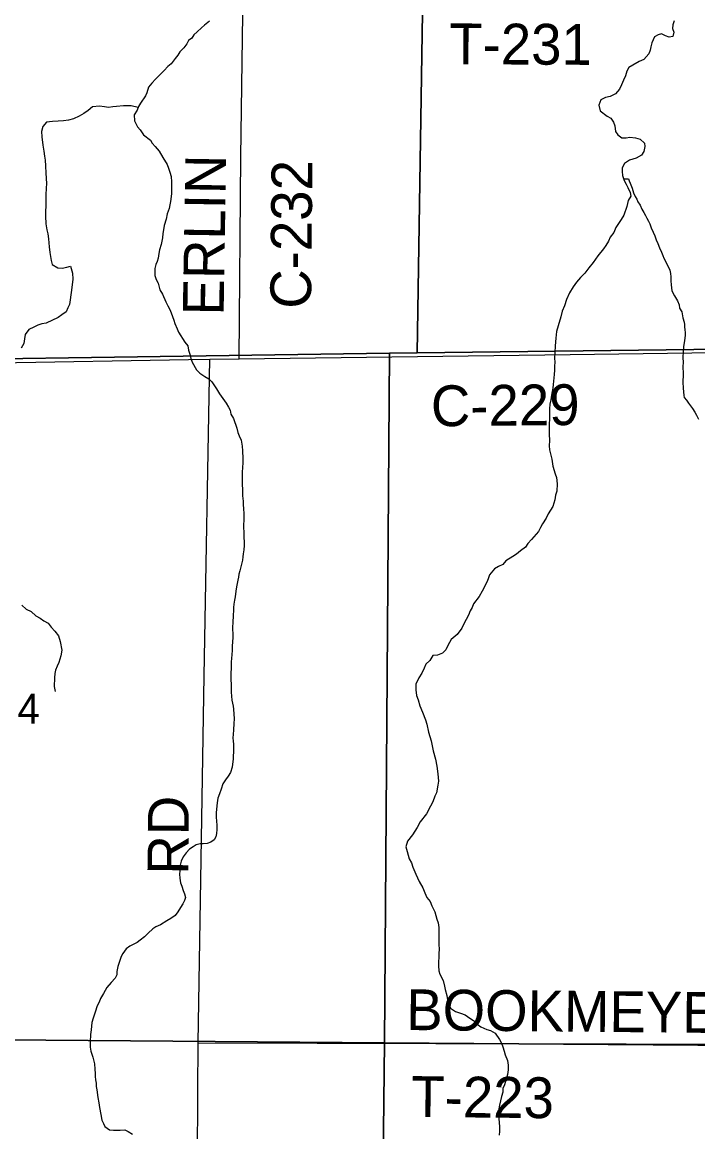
# Model space of a CAD drawing. Extents: x 0 to 34, y 0 to 22.
# Drawn here: x 28.499 to 29.44, y 18.79 to 20.335 of the extents above; entities that cross this region are included whole.
import ezdxf

# ---------------------------------------------------------------- set-up
doc = ezdxf.new("R2010")
doc.units = 0
for name, color, linetype in [('GM_X_County_Road', 7, 'Continuous'), ('GM_X_County_Road_Text', 7, 'Continuous'), ('GM_X_Minor_River', 7, 'Continuous'), ('GM_X_Section', 7, 'Continuous'), ('GM_X_Section_Text', 7, 'Continuous'), ('GM_X_Township_Road', 7, 'Continuous'), ('GM_X_Township_Road_Text', 7, 'Continuous')]:
    doc.layers.add(name, color=color, linetype=linetype)

msp = doc.modelspace()

# ---------------------------------------------------------------- linework, layer by layer
at = {"layer": 'GM_X_County_Road'}
for p, q in [((28.801, 19.8664), (29.2621, 19.8726)), ((28.0544, 19.8539), (28.7306, 19.8653)), ((28.7306, 19.8653), (28.76, 19.8658)), ((28.7525, 19.4249), (28.76, 19.8658)), ((28.76, 19.8658), (28.801, 19.8664))]:
    msp.add_line(p, q, dxfattribs=at)
for points in [[(28.801, 19.8664), (28.8036, 20.1477), (28.8064, 20.346), (28.8073, 20.3551), (28.8077, 20.357), (28.8082, 20.3596), (28.8093, 20.3615), (28.8128, 20.3664), (28.8151, 20.3682), (29.0351, 20.3742), (29.0559, 20.3746), (29.0644, 20.8767), (29.0647, 20.9)], [(29.2621, 19.8726), (30.0076, 19.8826), (30.0335, 19.8831)], [(28.739, 18.4414), (28.7392, 18.4501), (28.7405, 18.537), (28.7417, 18.6373), (28.7429, 18.7487), (28.7437, 18.8464), (28.7439, 18.9139), (28.7525, 19.4249)]]:
    msp.add_lwpolyline(points, dxfattribs=at)
at = {"layer": 'GM_X_Minor_River'}
for points in [[(28.7598, 20.3365), (28.7526, 20.3309), (28.7484, 20.3275), (28.7426, 20.3219), (28.738, 20.3178), (28.7353, 20.3129), (28.7307, 20.3095), (28.7284, 20.305), (28.7241, 20.2997), (28.7184, 20.2941), (28.7157, 20.2892), (28.7118, 20.2847), (28.7064, 20.2771), (28.7018, 20.2734), (28.6965, 20.2677), (28.6903, 20.2613), (28.6846, 20.2557), (28.6796, 20.2505), (28.675, 20.2448), (28.6726, 20.2369), (28.6707, 20.2327), (28.6637, 20.2225), (28.661, 20.218), (28.659, 20.2127), (28.6548, 20.2063), (28.6555, 20.1979), (28.6595, 20.1896), (28.6633, 20.1853), (28.6678, 20.1785), (28.6775, 20.1711), (28.6801, 20.1666), (28.6843, 20.1623), (28.6895, 20.1554), (28.6947, 20.147), (28.7007, 20.1371), (28.7029, 20.1321), (28.7047, 20.1264), (28.7062, 20.1203), (28.7068, 20.1131), (28.7067, 20.0968), (28.7062, 20.0926), (28.7054, 20.0854), (28.7046, 20.0809), (28.7034, 20.0756), (28.701, 20.0684), (28.6994, 20.0608), (28.6967, 20.0521), (28.6955, 20.0461), (28.695, 20.0411), (28.6942, 20.0347), (28.6926, 20.0256), (28.6902, 20.018), (28.6894, 20.0131), (28.6882, 20.0066), (28.687, 20.0021), (28.685, 19.9976), (28.6835, 19.9923), (28.6837, 19.9824), (28.6856, 19.9767), (28.6882, 19.9717), (28.6907, 19.9626), (28.6941, 19.9565), (28.6992, 19.9458), (28.7018, 19.9401), (28.7048, 19.934), (28.7081, 19.9256), (28.71, 19.9202), (28.7114, 19.9157), (28.7148, 19.908), (28.7166, 19.9035), (28.7255, 19.8897), (28.7297, 19.8843), (28.7307, 19.8783), (28.7329, 19.8714), (28.734, 19.8668), (28.7358, 19.8619), (28.7418, 19.8512), (28.7463, 19.8466), (28.7531, 19.842), (28.7587, 19.8385), (28.7628, 19.8343), (28.7658, 19.8301), (28.7696, 19.8247), (28.7737, 19.8178), (28.7785, 19.8113), (28.783, 19.8048), (28.7863, 19.7991), (28.7886, 19.7949), (28.7893, 19.7896), (28.793, 19.7835), (28.7978, 19.7697), (28.7992, 19.764), (28.8011, 19.7594)], [(29.4066, 20.3372), (29.4047, 20.3315), (29.4046, 20.3262), (29.4064, 20.3212), (29.4049, 20.3152), (29.3999, 20.3145), (29.3946, 20.3164), (29.3893, 20.3191), (29.3844, 20.3177), (29.3794, 20.3147), (29.3755, 20.3064), (29.374, 20.3011), (29.3735, 20.2962), (29.3716, 20.2909), (29.3647, 20.2833), (29.3578, 20.2804), (29.349, 20.2755), (29.3437, 20.2722), (29.341, 20.2669), (29.339, 20.2605), (29.3363, 20.2544), (29.3332, 20.248), (29.3308, 20.242), (29.325, 20.2352), (29.3174, 20.2318), (29.3113, 20.2304), (29.3048, 20.227), (29.3017, 20.2195), (29.3039, 20.2119), (29.3133, 20.2042), (29.3186, 20.2015), (29.3223, 20.1961), (29.3242, 20.1908), (29.3252, 20.1832), (29.3282, 20.1782), (29.3338, 20.1743), (29.3399, 20.1743), (29.3452, 20.175), (29.3528, 20.1741), (29.3592, 20.1722), (29.3652, 20.1668), (29.3659, 20.1619), (29.3647, 20.155), (29.3612, 20.1501), (29.354, 20.146), (29.3445, 20.1431), (29.3376, 20.1386), (29.3345, 20.1326), (29.3341, 20.1273), (29.3347, 20.1216), (29.3369, 20.1147), (29.3399, 20.1097), (29.3421, 20.1048), (29.3455, 20.0979), (29.3466, 20.093), (29.3427, 20.0869), (29.3407, 20.0786), (29.3368, 20.0665), (29.3329, 20.0605), (29.3291, 20.0548), (29.3256, 20.0492), (29.3225, 20.0424), (29.3178, 20.036), (29.3155, 20.0303), (29.3116, 20.0243), (29.3085, 20.0194), (29.3005, 20.01), (29.2939, 20.0005), (29.2878, 19.993), (29.2824, 19.9859), (29.2762, 19.9795), (29.2705, 19.9731), (29.2662, 19.9667)], [(28.6604, 20.2164), (28.6508, 20.2185), (28.6402, 20.2186), (28.6303, 20.2176), (28.625, 20.2173), (28.6193, 20.2166), (28.6136, 20.2174), (28.6064, 20.2182), (28.5969, 20.2172), (28.5908, 20.2123), (28.5846, 20.2082), (28.5782, 20.2045), (28.5705, 20.2004), (28.5633, 20.1986), (28.5565, 20.1979), (28.5489, 20.1972), (28.5413, 20.1969), (28.5329, 20.1958), (28.5275, 20.1898), (28.5259, 20.183), (28.5262, 20.1754), (28.5276, 20.164), (28.529, 20.1556), (28.5301, 20.1488), (28.5308, 20.1431), (28.5315, 20.1351), (28.5321, 20.1249), (28.5327, 20.1108), (28.5322, 20.104), (28.5321, 20.0949), (28.5317, 20.0858), (28.5314, 20.0649), (28.5321, 20.0546), (28.5331, 20.0459), (28.5346, 20.0406), (28.5356, 20.0333), (28.5366, 20.0223), (28.5377, 20.0147), (28.5384, 20.009), (28.5394, 20.0033), (28.5409, 19.9976), (28.5484, 19.9933), (28.5545, 19.9929), (28.561, 19.994), (28.5663, 19.9954), (28.5688, 19.9855), (28.5695, 19.9772), (28.5678, 19.962), (28.5649, 19.9423), (28.5626, 19.9374), (28.5603, 19.9321), (28.5541, 19.9276), (28.5492, 19.9242), (28.5324, 19.9161), (28.5263, 19.915), (28.5206, 19.9132), (28.5152, 19.9106), (28.5084, 19.9072), (28.503, 19.9001), (28.5022, 19.8944), (28.5013, 19.8876), (28.4975, 19.8811)], [(29.3361, 20.1172), (29.3432, 20.1171), (29.344, 20.1141), (29.3455, 20.111), (29.3482, 20.1042), (29.3501, 20.0978), (29.3524, 20.0924), (29.3547, 20.0887), (29.3563, 20.0852), (29.3593, 20.0803), (29.3616, 20.075), (29.3643, 20.0701), (29.3666, 20.0659), (29.3685, 20.0621), (29.3708, 20.058), (29.3728, 20.0542), (29.3747, 20.0489), (29.3774, 20.0428), (29.3797, 20.0379), (29.3816, 20.0322), (29.3839, 20.0269), (29.3862, 20.0212), (29.3889, 20.0151), (29.3908, 20.0102), (29.3924, 20.0068), (29.3943, 20.0034), (29.3966, 19.9981), (29.3989, 19.9939), (29.4008, 19.9897), (29.4016, 19.9852), (29.402, 19.9806), (29.402, 19.9745), (29.4024, 19.97), (29.4028, 19.9647), (29.4036, 19.9616), (29.4047, 19.9582), (29.4074, 19.9541), (29.4113, 19.9472), (29.4139, 19.9416), (29.4143, 19.937), (29.4174, 19.9317), (29.4178, 19.929), (29.419, 19.9237), (29.4205, 19.9173), (29.4209, 19.9142), (29.4213, 19.9116), (29.4217, 19.9063), (29.4221, 19.9036), (29.4221, 19.8994), (29.421, 19.8914), (29.4199, 19.8838), (29.4192, 19.8755), (29.4189, 19.869), (29.4193, 19.8603), (29.4189, 19.8565), (29.4189, 19.8531), (29.4193, 19.8481), (29.4194, 19.8447), (29.419, 19.8341), (29.4191, 19.8257), (29.4203, 19.8155), (29.4207, 19.8124), (29.4237, 19.809), (29.4268, 19.8049), (29.4321, 19.7973), (29.4356, 19.792), (29.4379, 19.7878), (29.4406, 19.7825)], [(29.2662, 19.9667), (29.2612, 19.9584), (29.2569, 19.9489), (29.2542, 19.9402), (29.2507, 19.933), (29.2487, 19.9247), (29.2451, 19.9126), (29.2431, 19.9047), (29.2419, 19.8952), (29.241, 19.8846), (29.2405, 19.8751), (29.24, 19.8671), (29.2404, 19.8622), (29.2403, 19.8557), (29.2399, 19.8508), (29.2398, 19.8447), (29.2394, 19.8398), (29.2381, 19.8307), (29.2377, 19.8258), (29.2369, 19.8208), (29.2357, 19.8159), (29.2348, 19.8095), (29.2336, 19.8034), (29.2332, 19.797), (29.2328, 19.7617), (29.233, 19.7525), (29.2326, 19.7453), (29.2333, 19.7396), (29.2351, 19.7324), (29.2362, 19.7267), (29.238, 19.7172), (29.2412, 19.7061), (29.2427, 19.7012), (29.2437, 19.6924), (29.2432, 19.6822), (29.2413, 19.6765), (29.2405, 19.6701), (29.2377, 19.661), (29.2315, 19.6504), (29.2284, 19.6444), (29.2234, 19.6365), (29.2207, 19.6316), (29.2176, 19.6259), (29.208, 19.615), (29.203, 19.6094), (29.1995, 19.6041), (29.1926, 19.5992), (29.1872, 19.5944), (29.1819, 19.591), (29.1723, 19.585), (29.1681, 19.5801), (29.162, 19.5772), (29.1567, 19.5738), (29.1497, 19.5655), (29.1478, 19.5602), (29.1458, 19.5553), (29.1392, 19.5429), (29.135, 19.5353), (29.1273, 19.5255), (29.1253, 19.5202), (29.1226, 19.5153), (29.1203, 19.5097), (29.1172, 19.5036), (29.1137, 19.4976), (29.111, 19.4915), (29.1044, 19.4825), (29.0964, 19.4758), (29.0917, 19.4671), (29.089, 19.461), (29.084, 19.4565), (29.0771, 19.4539), (29.0707, 19.4533), (29.0664, 19.4465), (29.0611, 19.4412), (29.0587, 19.4359), (29.0556, 19.4287), (29.051, 19.4223), (29.0471, 19.4133), (29.047, 19.4057), (29.0481, 19.3977), (29.0503, 19.3916), (29.0528, 19.3832), (29.0561, 19.3745), (29.0606, 19.3638), (29.0624, 19.3577), (29.0649, 19.3466), (29.0686, 19.3345), (29.0714, 19.3204), (29.0744, 19.309), (29.0765, 19.2994), (29.0775, 19.2884), (29.0786, 19.2782), (29.0777, 19.2729), (29.0757, 19.2623), (29.0734, 19.2573), (29.0706, 19.2498), (29.0675, 19.2437), (29.0617, 19.2328), (29.0532, 19.2215), (29.049, 19.214), (29.0455, 19.2087)], [(28.8011, 19.7594), (28.804, 19.753), (28.8051, 19.745), (28.8058, 19.7385), (28.8064, 19.7275), (28.8063, 19.7218), (28.8059, 19.715), (28.8054, 19.7085), (28.8052, 19.6915), (28.8055, 19.6846), (28.8058, 19.6755), (28.8065, 19.6683), (28.8068, 19.6637), (28.8071, 19.6577), (28.8074, 19.6512), (28.8077, 19.644), (28.8072, 19.633), (28.8075, 19.6235), (28.8078, 19.617), (28.8081, 19.6121), (28.808, 19.6064), (28.8076, 19.6003), (28.8068, 19.595), (28.8063, 19.5905), (28.8055, 19.5859), (28.8019, 19.5712), (28.8008, 19.5666), (28.8, 19.5624), (28.7991, 19.5583), (28.7983, 19.5534), (28.7975, 19.5488), (28.7963, 19.5431), (28.7955, 19.5352), (28.7947, 19.5306), (28.7938, 19.5246), (28.7934, 19.52), (28.793, 19.5151), (28.7925, 19.5105), (28.7925, 19.5063), (28.7921, 19.5022), (28.7919, 19.49), (28.7922, 19.4836), (28.7922, 19.4779), (28.7917, 19.4726), (28.7913, 19.4657), (28.7912, 19.4604), (28.7903, 19.449), (28.7899, 19.4445), (28.7896, 19.4198), (28.7899, 19.413), (28.7898, 19.4024), (28.7908, 19.391), (28.7926, 19.383), (28.7933, 19.3788), (28.7939, 19.3651), (28.7938, 19.3587), (28.793, 19.3499), (28.7925, 19.3435), (28.7921, 19.3386), (28.7928, 19.334), (28.7931, 19.3298), (28.7934, 19.3192), (28.7929, 19.3131), (28.7929, 19.3089), (28.7917, 19.3021), (28.7912, 19.298), (28.7889, 19.2904), (28.7858, 19.2855), (28.7819, 19.2802), (28.7785, 19.2746), (28.7761, 19.2674), (28.7737, 19.2609), (28.7714, 19.2549), (28.7706, 19.2484), (28.7689, 19.2348), (28.7692, 19.228), (28.7698, 19.2169), (28.7701, 19.2109), (28.7697, 19.2056), (28.7685, 19.201), (28.7662, 19.1965), (28.7616, 19.1935), (28.7566, 19.1917), (28.7509, 19.191), (28.7468, 19.191), (28.7411, 19.1895), (28.7369, 19.1869), (28.7319, 19.1836), (28.7273, 19.1787), (28.7231, 19.173), (28.7203, 19.167), (28.7187, 19.1613), (28.7183, 19.1537), (28.7182, 19.1488), (28.7185, 19.1431), (28.7196, 19.137), (28.7211, 19.1321), (28.7233, 19.126), (28.7251, 19.1214), (28.7262, 19.1164), (28.725, 19.1123)], [(28.4983, 19.5235), (28.5047, 19.5178), (28.5115, 19.5147), (28.5182, 19.5085), (28.5239, 19.5054), (28.5292, 19.5016), (28.5352, 19.4985), (28.5393, 19.4927), (28.5446, 19.4874), (28.5494, 19.4809), (28.552, 19.4729), (28.5541, 19.4607), (28.5529, 19.4527), (28.5498, 19.4437), (28.5478, 19.4387), (28.5455, 19.4331), (28.5443, 19.4282), (28.5438, 19.4221), (28.5437, 19.4103), (28.5449, 19.4034)], [(29.0455, 19.2087), (29.0424, 19.2038), (29.0355, 19.1947), (29.0331, 19.1868), (29.035, 19.1803), (29.0379, 19.17), (29.0408, 19.1647), (29.043, 19.1586), (29.0471, 19.1487), (29.0519, 19.1388), (29.0567, 19.1296), (29.0597, 19.1227), (29.0623, 19.1163), (29.0672, 19.1109), (29.0694, 19.1048), (29.0734, 19.0964), (29.0764, 19.0861), (29.0782, 19.0812), (29.0789, 19.0747), (29.0792, 19.069), (29.079, 19.0515), (29.0793, 19.044), (29.0789, 19.039), (29.0786, 19.0212), (29.079, 19.0143), (29.0804, 19.0094), (29.0849, 19.0006), (29.0871, 18.993), (29.0881, 18.9881), (29.0903, 18.9801), (29.091, 18.974), (29.0913, 18.9687), (29.0954, 18.9622), (29.1022, 18.9575), (29.1094, 18.9552), (29.1158, 18.9528), (29.1222, 18.9482), (29.1275, 18.9451), (29.1323, 18.9398), (29.1376, 18.9363), (29.1459, 18.9324), (29.1508, 18.9312), (29.1576, 18.9273), (29.1636, 18.9185), (29.1662, 18.9136), (29.168, 18.9082), (29.1699, 18.9025), (29.1713, 18.8972), (29.1746, 18.8896), (29.1757, 18.8831), (29.1756, 18.8763), (29.1748, 18.8698), (29.1724, 18.8619), (29.1704, 18.8555), (29.1681, 18.8502), (29.1681, 18.8452), (29.1665, 18.8392), (29.1633, 18.8274), (29.1621, 18.8199), (29.1624, 18.8138), (29.1627, 18.8088), (29.1637, 18.7971), (29.1636, 18.791), (29.1632, 18.7853)], [(28.725, 19.1123), (28.7227, 19.1074), (28.7192, 19.1025), (28.7157, 19.0964), (28.7119, 19.0915), (28.7058, 19.0871), (28.7004, 19.0837), (28.6916, 19.0785), (28.6851, 19.0755), (28.6809, 19.0725), (28.6744, 19.0665), (28.6691, 19.0616), (28.6633, 19.0568), (28.6591, 19.0538), (28.6545, 19.0515), (28.6488, 19.0486), (28.6438, 19.0448), (28.6392, 19.0384), (28.6369, 19.0343), (28.6345, 19.0271), (28.6322, 19.0203), (28.6309, 19.0131), (28.6309, 19.0085), (28.6286, 19.004), (28.6228, 18.998), (28.6167, 18.9912), (28.612, 18.9829), (28.6081, 18.9757), (28.6062, 18.9705), (28.6035, 18.9655), (28.6007, 18.9568), (28.5976, 18.9485), (28.596, 18.9421), (28.5951, 18.9319), (28.5943, 18.9254), (28.5938, 18.9155), (28.5937, 18.908), (28.5944, 18.9026), (28.5973, 18.8939), (28.5995, 18.8847), (28.6002, 18.8771), (28.6005, 18.8711), (28.6008, 18.8669), (28.6011, 18.8623), (28.6019, 18.8578), (28.6022, 18.8532), (28.6029, 18.8486), (28.6043, 18.838), (28.6057, 18.8304), (28.6068, 18.8239), (28.6086, 18.8144), (28.61, 18.8064), (28.6122, 18.8015), (28.6141, 18.7973), (28.6205, 18.793), (28.6261, 18.7922), (28.6307, 18.7922), (28.6352, 18.7925), (28.6417, 18.7928), (28.6466, 18.7905), (28.6526, 18.7866)]]:
    msp.add_lwpolyline(points, dxfattribs=at)
at = {"layer": 'GM_X_Section'}
for points in [[(30.0649, 20.8926), (30.0369, 19.8872), (30.0112, 19.8862), (29.0488, 19.8748), (29.0645, 20.8822)], [(29.0645, 20.8822), (29.0488, 19.8748), (29.0105, 19.8743), (28.0523, 19.8602), (28.0611, 20.8611)], [(30.0112, 19.8862), (30.0004, 18.9065), (29.0034, 18.9139), (29.0105, 19.8743), (29.0488, 19.8748)], [(29.0105, 19.8743), (29.0034, 18.9139), (28.001, 18.9217), (28.0159, 19.8585), (28.0523, 19.8602)]]:
    msp.add_lwpolyline(points, close=True, dxfattribs=at)
for points in [[(28.4862, 17.9139), (27.9928, 17.9132), (28.001, 18.9217), (29.0034, 18.9139), (28.9945, 18.1387)], [(28.9945, 18.1387), (29.0034, 18.9139), (30.0004, 18.9065), (29.9873, 18.1387)]]:
    msp.add_lwpolyline(points, dxfattribs=at)
at = {"layer": 'GM_X_Township_Road'}
for p, q in [((28.7439, 18.9139), (29.2406, 18.9128)), ((29.2406, 18.9128), (29.3398, 18.9126)), ((29.3398, 18.9126), (30.0045, 18.9111))]:
    msp.add_line(p, q, dxfattribs=at)

# ---------------------------------------------------------------- texts
at = {"layer": 'GM_X_County_Road_Text'}
for s, rotation, p in [('ERLIN', 89.0651, (28.7794, 19.9265)), ('C-232', 89.4494, (28.9011, 19.936)), ('C-229', 0.5511, (29.0683, 19.7724)), ('RD', 89.5063, (28.7302, 19.148))]:
    msp.add_text(s, height=0.05682, rotation=rotation, dxfattribs=at).set_placement(p)
at = {"layer": 'GM_X_Section_Text'}
msp.add_text('4', height=0.0419, rotation=0, dxfattribs=at).set_placement((28.4924, 19.3582))
at = {"layer": 'GM_X_Township_Road_Text'}
for s, rotation, p in [('T-231', 359.7193, (29.0935, 20.2767)), ('BOOKMEYER', 359.4573, (29.0335, 18.9318)), ('T-223', 359.4381, (29.0406, 18.8109))]:
    msp.add_text(s, height=0.05682, rotation=rotation, dxfattribs=at).set_placement(p)

doc.saveas('drawing.dxf')
